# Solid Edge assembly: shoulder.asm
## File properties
Author: nakano
Template: Iso Metric Assembly.asm
Last saved by: nakano
Revision: 24
Application: Solid Edge
Username: nakano
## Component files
asb-205.par
asb-203.par
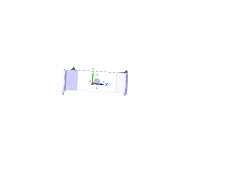
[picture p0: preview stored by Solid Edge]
